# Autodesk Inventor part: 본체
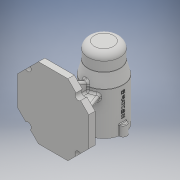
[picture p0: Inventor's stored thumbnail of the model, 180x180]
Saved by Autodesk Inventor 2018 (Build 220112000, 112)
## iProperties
Created: 2019-12
Part Number: 본체
Material: Generic
Document SubType Name: Modeling
Designer: Administrator
Density: 1 g/cm^3
Appearance: Default
Author: Administrator
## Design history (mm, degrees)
sketch "스케치1"
  geometry: L1 (-23.196, -56)-(-56, -23.196); L2 (-56, -23.196)-(-56, 23.196); L3 (-56, 23.196)-(-23.196, 56); L4 (-23.196, 56)-(23.196, 56); L5 (23.196, 56)-(56, 23.196); L6 (56, 23.196)-(56, -23.196); L7 (56, -23.196)-(23.196, -56); L8 (23.196, -56)-(-23.196, -56); 2 further points
  constraints: 16 end point, 1 coincident, 1 horizontal, 17 other
  dimensions: "d0" = 112 distance between parallel lines of L2 L6
extrude "돌출1" new body sketch "스케치1" distance "d1" = 10; taper "d2" = 0 deg
sketch "스케치2"
  geometry: L1 (0, 0)-(10, 0); L2 (10, -23.196)-(10, -56) reference; L3 (80, -56)-(110, -56); L4 (110, -56)-(110, 11); L5 (110, 11)-(80, 11); L6 (80, 11)-(80, -56); L7 (80, 11)-(110, 11); L8 (105, 31)-(80, 31); L9 (80, 31)-(80, 11); L10 (80, 31)-(105, 31); L11 (105, 31)-(105, 56); L12 (105, 56)-(80, 56); L13 (80, 56)-(80, 31); L14 (105, 31)-(110, 11)
  constraints: 26 end point, 5 parallel, 4 horizontal, 2 perpendicular, 2 point on line
  dimensions: "d5" = 112 distance between parallel lines of L3 L12; "d6" = 60 diameter of L4 L6; "d7" = 50 diameter of L11 L13; "d8" = 25 distance between parallel lines of L8 L12; "d9" = 45 distance between parallel lines of L5 L12
revolve "회전1" sketch "스케치2" stored, may be unused: angle "d10" = 90 deg
sketch "스케치3"
  geometry: L1 (5.391, 38)-(60.901, 12.115); L2 (60.901, 12.115)-(60.901, -31); L3 (10, 23.196)-(10, 56) reference; L4 (60.901, -31)-(5.391, -31); L5 (5.391, -31)-(5.391, 38); L6 (0, -56)-(10, -56) reference; L7 (0, 56)-(10, 56) reference; 1 further point
  constraints: 8 end point, 2 perpendicular, 1 parallel
  dimensions: "d11" = 115 deg angle of L3 L1; "d12" = 25 distance between parallel lines of L4 L6; "d13" = 18 distance from line of L1.start L7
extrude "돌출2" join sketch "스케치3" stored distance "d14" = 8; taper "d15" = 0 deg
sketch "스케치4"
  geometry: L1 (36, 5.894)-(16.107, 60.549); L2 (16.107, 60.549)-(-16.107, 60.549); L3 (23.196, 10)-(56, 10) reference; L4 (-16.107, 60.549)-(-36, 5.894); L5 (-36, 5.894)-(36, 5.894); L6 (-56, 10)-(-23.196, 10) reference; L7 (56, 0)-(56, 10) reference; L8 (-56, 0)-(-56, 10) reference; 1 further point
  constraints: 8 end point, 2 parallel
  dimensions: "d16" = 110 deg angle of L6 L4; "d17" = 110 deg angle of L3 L1; "d18" = 20 distance from line of L1.start L7; "d19" = 20 distance from line of L4.end L8
extrude "돌출3" join sketch "스케치4" stored distance "d20" = 8; taper "d21" = 0 deg
sketch "스케치5"
  geometry: L1 (55, 56)-(105, 56) reference; L2 (50, -56)-(110, -56) reference; L3 (80, -56)-(101, -56); L4 (101, -56)-(101, -41); L5 (101, -41)-(80, -41); L6 (80, -41)-(80, -56); L7 (80, -41)-(101, -41); L8 (104, -38)-(104, 10); L9 (101, 13)-(80, 13); L10 (80, 13)-(80, -41); L11 (80, 13)-(101, 13); L12 (101, 13)-(101, 24.7); L13 (100.7, 25)-(80, 25); L14 (80, 25)-(80, 13); L15 (80, 25)-(97.5, 25); L16 (97.5, 25)-(97.5, 42.7); L17 (97.2, 43)-(80, 43); L18 (80, 43)-(80, 25); L19 (80, 43)-(96, 43); L20 (96, 43)-(96, 46.7); L21 (95.7, 47)-(80, 47); L22 (80, 47)-(80, 43); L23 (80, 47)-(90.5, 47); L24 (90.5, 47)-(90.5, 47); L25 (87.5, 50)-(80, 50); L26 (80, 50)-(80, 47); A1 r 3 centre (87.5, 47) between (90.5, 47) and (87.5, 50); A2 r 0.3 centre (95.7, 46.7) between (96, 46.7) and (95.7, 47); A3 r 0.3 centre (97.2, 42.7) between (97.5, 42.7) and (97.2, 43); A4 r 0.3 centre (100.7, 24.7) between (101, 24.7) and (100.7, 25); A5 r 3 centre (101, 10) between (104, 10) and (101, 13); A6 r 3 centre (101, -38) between (101, -41) and (104, -38); 4 further points
  constraints: 48 end point, 12 parallel, 12 point on circle, 12 tangent, 7 point on line, 6 centre point, 6 horizontal, 6 perpendicular, 3 equal radius, 1 midpoint
  dimensions: "d22" = 15 distance between parallel lines of L2 L5; "d23" = 54 distance between parallel lines of L5 L11; "d24" = 12 distance between parallel lines of L11 L13; "d25" = 18 distance between parallel lines of L15 L17; "d26" = 4 distance between parallel lines of L17 L21; "d27" = 3 distance between parallel lines of L21 L25; "d28" = 42 diameter of L4 L6; "d29" = 48 diameter of L8 L10; "d30" = 35 diameter of L16 L18; "d31" = 32 diameter of L20 L22; "d32" = 21 diameter of L24 L26; "d33" = 3 radius of A1; "d34" = 0.3 radius of A2; "d58" = 3 radius of A5 (derived)
revolve "회전2" sketch "스케치5" stored, may be unused: angle "d35" = 90 deg
sketch "스케치6"
  geometry: C1 r 6 at (0, 30); 2 further points
  constraints: 1 centre point, 1 vertical alignment, 1 other
  dimensions: "d36" = 12 diameter of C1
extrude "돌출4" join sketch "스케치6" distance "d37" = 16; taper "d38" = 0 deg
fillet "모깎기1" dims "d39" = 1
sketch "스케치7"
  geometry: C1 r 10.5 at (0, -30) reference; A1 r 30 centre (0, -30) between (0, 0) and (30, -30); 3 further points
  constraints: 4 point on circle, 1 centre point, 1 coincident
  dimensions: "d43" = 60 diameter of A1
hole "구멍1" sketch "스케치7" at (0, 0), (30, -30), (-30, -30) diameter "d44" = 3.242; stored, may be unused: countersink angle "d48" = 90 deg, drill point angle "d50" = 118 deg; dims "d45" = 8, "d46" = 4, "d47" = 2, "d49" = 11
sketch "스케치8"
  geometry: L1 (-56, 23.196)-(-23.196, 56) reference; L2 (23.196, 56)-(56, 23.196) reference; L3 (39.598, 39.598)-(-39.598, -39.598); L4 (-23.196, -56)-(-56, -23.196) reference; L5 (-39.598, 39.598)-(39.598, -39.598); L6 (56, -23.196)-(23.196, -56) reference; C1 r 5 at (39.598, -39.598); C2 r 5 at (39.598, 39.598); C3 r 5 at (-39.598, 39.598); C4 r 5 at (-39.598, -39.598); 1 further point
  constraints: 4 centre point, 4 coincident, 4 end point, 4 midpoint
  dimensions: "d51" = 10 diameter of C1; "d52" = 10 diameter of C2; "d53" = 10 diameter of C3; "d54" = 10 diameter of C4
extrude "돌출5" cut sketch "스케치8" distance "d55" = 30; taper "d56" = 0 deg
fillet "모깎기2" dims "d57" = 10
chamfer "모따기1" distance "d59" = 1; stored, may be unused: second distance "d60" = 2, angle "d61" = 45 deg
fillet "모깎기3" dims "d62" = 3
fillet "모깎기4" dims "d63" = 3
node "작업 평면1"
sketch "스케치9"
  geometry: L1 (-22, -33.5)-(22, -33.5) reference; 3 further points
  constraints: 1 midpoint, 1 other
  dimensions: "d64" = 0 horizontal distance of point (0, -33.5) point (0, 7.5); "d65" = 41 distance from line of L1 point (0, 7.5)
feature "엠보싱1" sketch "스케치9" dims "d0" = 112, "d5" = 112, "d6" = 60, "d7" = 50, "d8" = 25, "d9" = 45, "d66" = 0.5, "d67" = 0
node "솔리드1"
pattern_circular "원형 패턴1" dims angle "d41" = 360 deg
